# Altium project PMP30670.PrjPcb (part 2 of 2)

## Sheet PMP30670RevB_1.SchDoc: PMP30670RevA_1
size A3; Date: Not shown in title block; ApprovedBy: Not shown in title block; CheckedBy: Not shown in title block; Author: Not shown in title block; CompanyName: Not shown in title block; DrawnBy: M Zehendner; Engineer: Not shown in title block; Organization: Not shown in title block; Address1: Not shown in title block; Address2: Not shown in title block; Address3: Not shown in title block; Address4: Not shown in title block; DocumentNumber: 1; Revision: Use project parameter SCH_Rev; SheetNumber: 1; SheetTotal: 3; PageSetup: Record=PageOptions¦CenterHorizontal=True¦CenterVertical=True¦PrintScale=0.70¦XCorrection=1.00¦YCorrection=1.00¦PrintKind=0¦BorderSize=5000000¦LeftOffset=0¦BottomOffset=0¦Orientation=2¦PaperLength=1000¦PaperWidth=1000¦Scale=100¦PaperSource=15¦PrintQuality=600¦MediaType=1¦DitherType=10¦PaperKind=A4¦PrintScaleMode=1
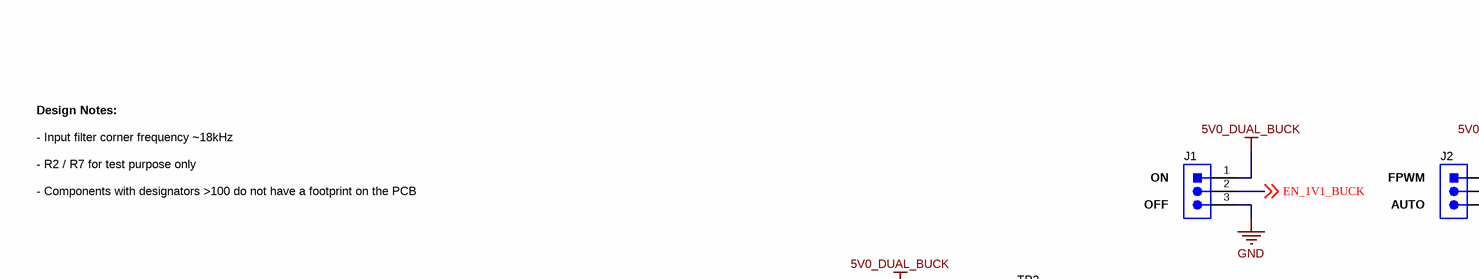
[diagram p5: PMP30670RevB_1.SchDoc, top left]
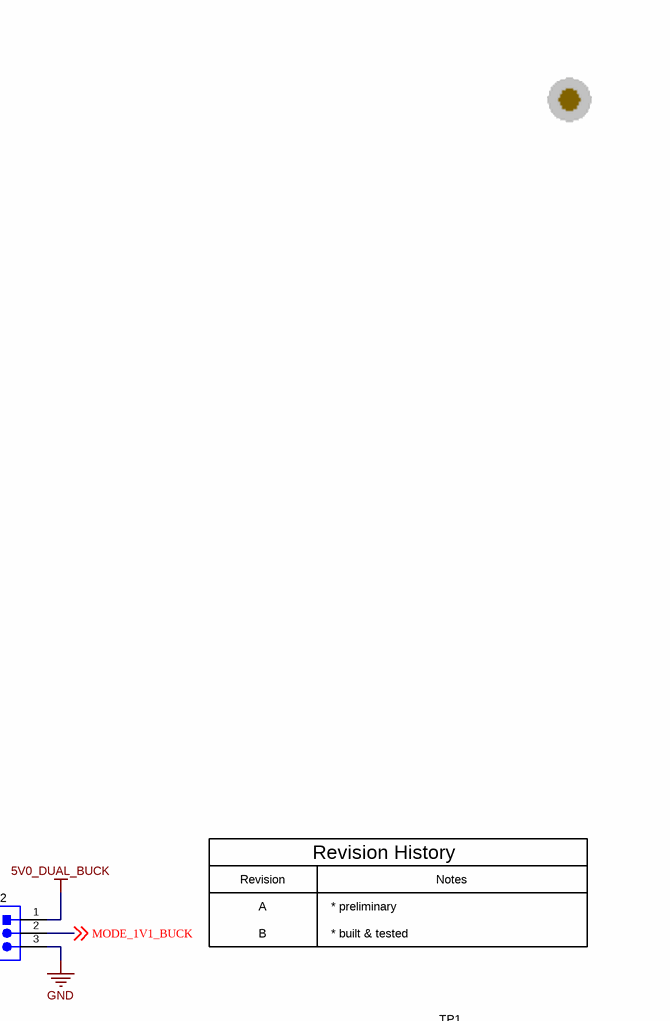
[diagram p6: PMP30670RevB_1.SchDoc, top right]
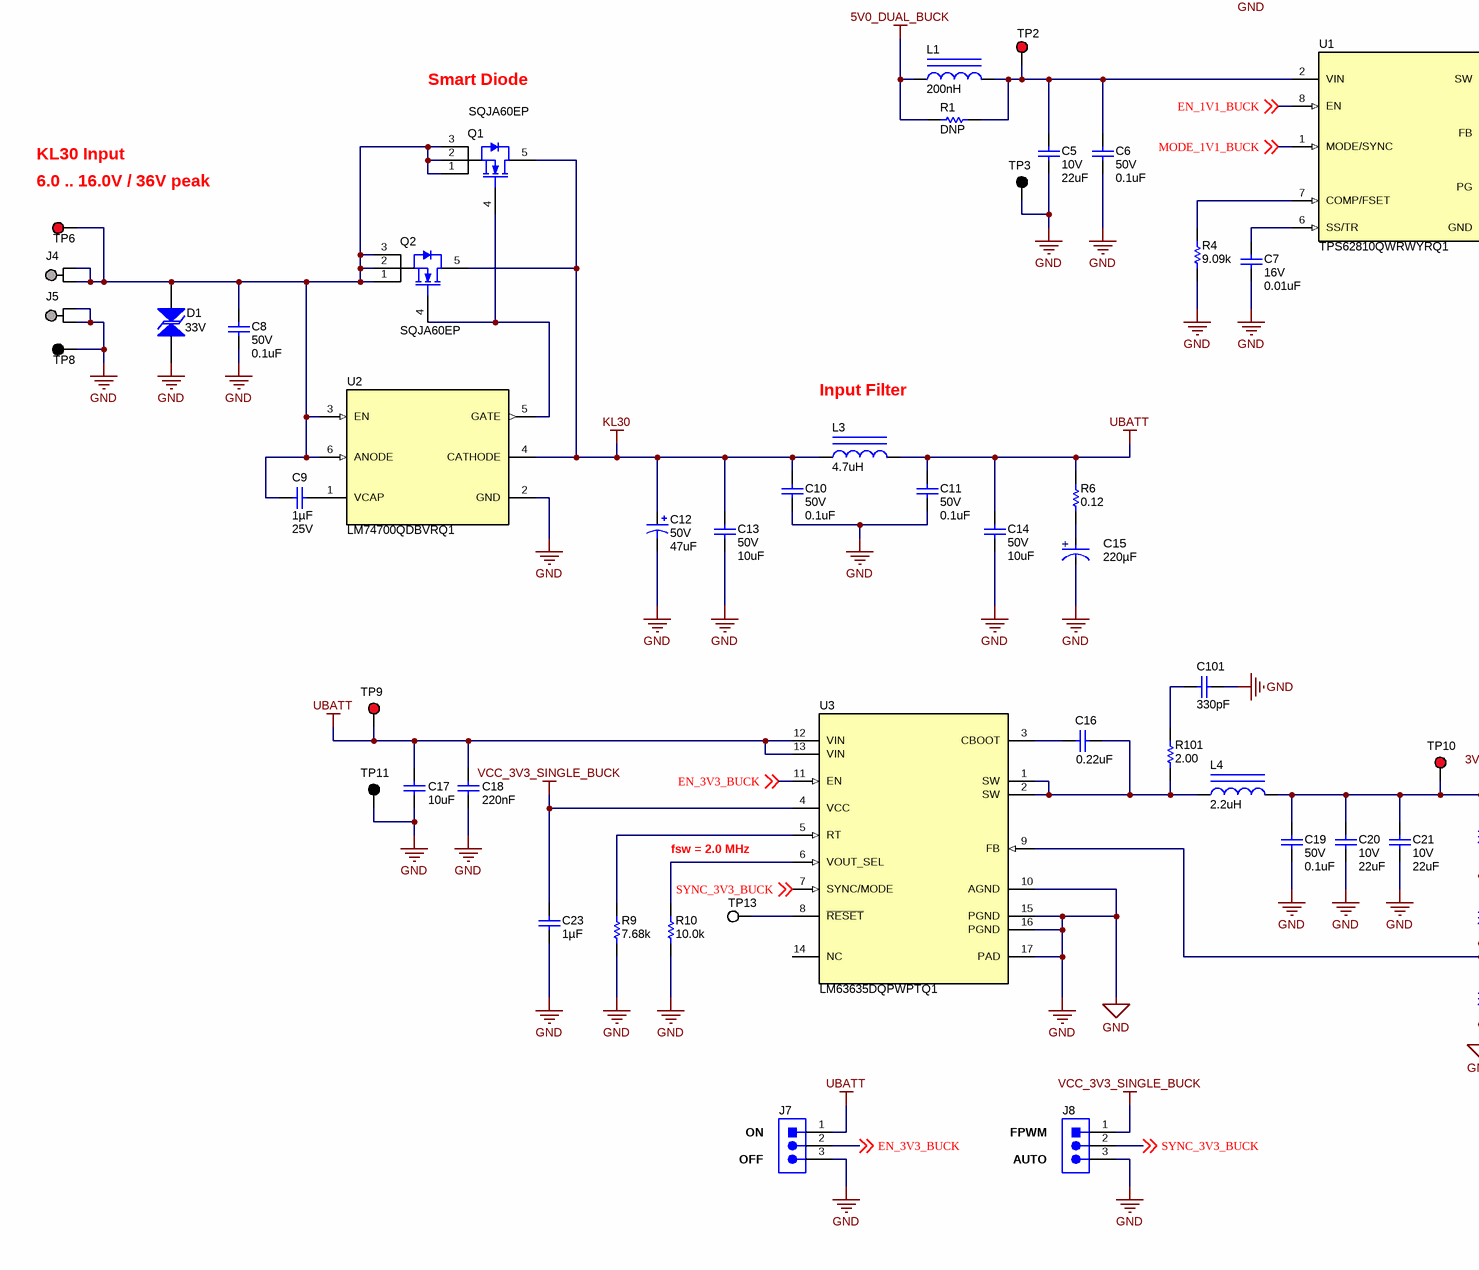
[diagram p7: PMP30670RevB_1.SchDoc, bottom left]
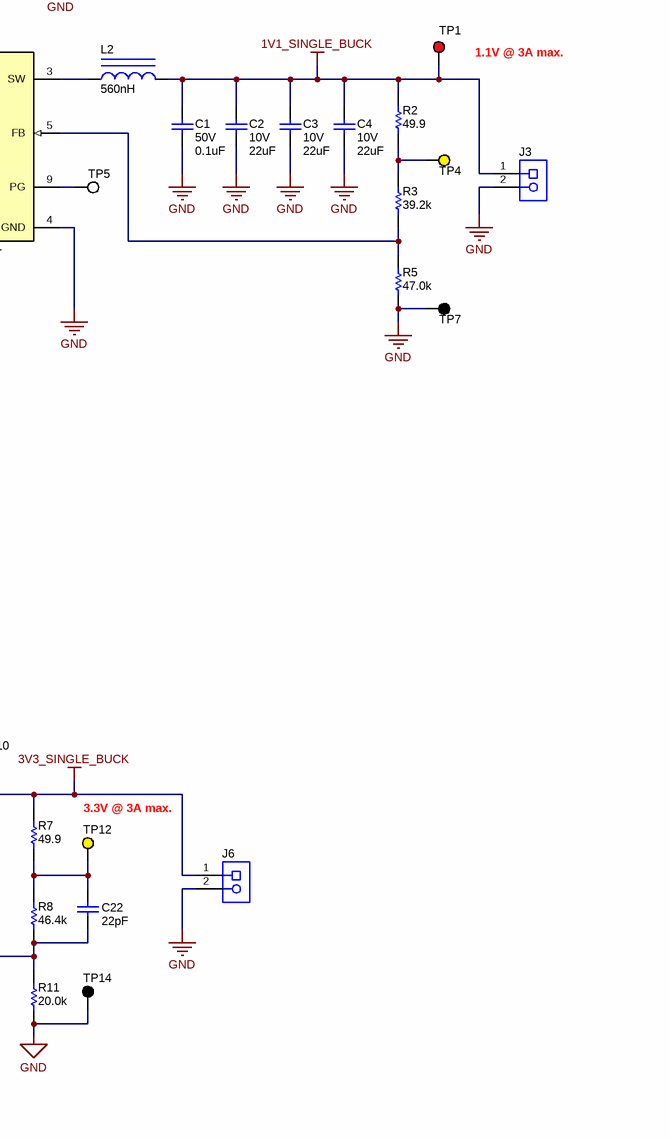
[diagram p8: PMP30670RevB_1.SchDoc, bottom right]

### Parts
C1  VDC_V: 50V  ValueDisplayed: 0.1uF  [0402]  (hidden comment: GRM155R71H104ME14D)
C2  VDC_V: 10V  ValueDisplayed: 22uF  [1206_180]  (hidden comment: GCM31CR71A226KE02)
C3  VDC_V: 10V  ValueDisplayed: 22uF  [1206_180]  (hidden comment: GCM31CR71A226KE02)
C4  VDC_V: 10V  ValueDisplayed: 22uF  [1206_180]  (hidden comment: GCM31CR71A226KE02)
C5  VDC_V: 10V  ValueDisplayed: 22uF  [1206_180]  (hidden comment: GCM31CR71A226KE02)
C6  VDC_V: 50V  ValueDisplayed: 0.1uF  [0402]  (hidden comment: GRM155R71H104ME14D)
C7  VDC_V: 16V  ValueDisplayed: 0.01uF  [0402]  (hidden comment: GRM155R71C103KA01D)
C8  VDC_V: 50V  ValueDisplayed: 0.1uF  [0402]  (hidden comment: GRM155R71H104ME14D)
C9  Cap_F: 1µF  VDC_V: 25V  [0603]  (hidden comment: GRM188R71E105KA12D)
C10  VDC_V: 50V  ValueDisplayed: 0.1uF  [0402]  (hidden comment: GRM155R71H104ME14D)
C11  VDC_V: 50V  ValueDisplayed: 0.1uF  [0402]  (hidden comment: GRM155R71H104ME14D)
C12  VDC_V: 50V  ValueDisplayed: 47uF  [SM_RADIAL_D8]  (hidden comment: EEE-FK1H470XP)
C13  VDC_V: 50V  ValueDisplayed: 10uF  [1210_270]  (hidden comment: GRM32ER71H106KA12L)
C14  VDC_V: 50V  ValueDisplayed: 10uF  [1210_270]  (hidden comment: GRM32ER71H106KA12L)
C15  Cap_F: 220µF  [FP-EEVTG1H221Q_RADIAL-Recommended_Land_Pattern]  (hidden comment: EEVTG1H221Q)
C16  ValueDisplayed: 0.22uF  [0402]  (hidden comment: GRM155R71C224KA12D)
C17  ValueDisplayed: 10uF  [1210_270]  (hidden comment: GRM32ER71H106KA12L)
C18  Cap_F: 220nF  [0603]  (hidden comment: GRM188R71H224KAC4D)
C19  VDC_V: 50V  ValueDisplayed: 0.1uF  [0402]  (hidden comment: GRM155R71H104ME14D)
C20  VDC_V: 10V  ValueDisplayed: 22uF  [1210_270]  (hidden comment: GRM32ER71A226ME20L)
C21  VDC_V: 10V  ValueDisplayed: 22uF  [1210_270]  (hidden comment: GRM32ER71A226ME20L)
C22  ValueDisplayed: 22pF  [0402]  (hidden comment: GRM1555C1H220FA01D)
C23  Cap_F: 1µF  [0805_HV]  (hidden comment: GRM21BR71A105KA01L)
C101  Cap_F: 330pF  [0603]  (hidden comment: GRM188R72E331KW07D)
D1  value 33V  [SMB-Bi]  (hidden comment: SMBJ33CA-13-F)
J1  800-10-003-10-001000  [Mill-Max_800-10-003-10-001000]  (value not drawn)
J2  800-10-003-10-001000  [Mill-Max_800-10-003-10-001000]  (value not drawn)
J3  691 101 710 002  [Wurth_691101710002]  (value not drawn)
J4  973 582-101  [HIRSCHMANN_973 582-101]  (value not drawn)
J5  973 582-100  [HIRSCHMANN_973 582-100]  (value not drawn)
J6  691 101 710 002  [Wurth_691101710002]  (value not drawn)
J7  800-10-003-10-001000  [Mill-Max_800-10-003-10-001000]  (value not drawn)
J8  800-10-003-10-001000  [Mill-Max_800-10-003-10-001000]  (value not drawn)
L1  ValueDisplayed: 200nH  [XPL2010]  (hidden comment: XPL2010-201MLB)
L2  ValueDisplayed: 560nH  [XEL4020]  (hidden comment: XEL4020-561MEB)
L3  ValueDisplayed: 4.7uH  [XAL1060]  (hidden comment: XAL1060-472MEB)
L4  ValueDisplayed: 2.2uH  [XAL5030]  (hidden comment: XEL5030-222MEB)
Q1  SQJA60EP  [PowerPAK_SO-8L]
Q2  SQJA60EP  [PowerPAK_SO-8L]
R1  ValueDisplayed: DNP  [1206]  (hidden comment: ERJ-8GEY0R00V)
R2  ValueDisplayed: 49.9  [0603]  (hidden comment: CRCW060349R9FKEA)
R3  ValueDisplayed: 39.2k  [0603]  (hidden comment: CRCW060339K2FKEA)
R4  ValueDisplayed: 9.09k  [0603]  (hidden comment: CRCW06039K09FKEA)
R5  ValueDisplayed: 47.0k  [0603]  (hidden comment: CRCW060347K0FKEA)
R6  ValueDisplayed: 0.12  [0603]  (hidden comment: ERJ-3RSFR12V)
R7  ValueDisplayed: 49.9  [0603]  (hidden comment: CRCW060349R9FKEA)
R8  ValueDisplayed: 46.4k  [0603]  (hidden comment: CRCW060346K4FKEA)
R9  ValueDisplayed: 7.68k  [0603]  (hidden comment: CRCW06037K68FKEA)
R10  ValueDisplayed: 10.0k  [0603]  (hidden comment: CRCW060310K0FKEA)
R11  ValueDisplayed: 20.0k  [0603]  (hidden comment: CRCW060320K0FKEA)
R101  ValueDisplayed: 2.00  [0603]  (hidden comment: CRCW06032R00FKEA)
TP1  5010  [Keystone5010]  (value not drawn)
TP2  5010  [Keystone5010]  (value not drawn)
TP3  5011  [Keystone5011]  (value not drawn)
TP4  5014  [Keystone5014]  (value not drawn)
TP5  5012  [Keystone5012]  (value not drawn)
TP6  5010  [Keystone5010]  (value not drawn)
TP7  5011  [Keystone5011]  (value not drawn)
TP8  5011  [Keystone5011]  (value not drawn)
TP9  5010  [Keystone5010]  (value not drawn)
TP10  5010  [Keystone5010]  (value not drawn)
TP11  5011  [Keystone5011]  (value not drawn)
TP12  5014  [Keystone5014]  (value not drawn)
TP13  5012  [Keystone5012]  (value not drawn)
TP14  5011  [Keystone5011]  (value not drawn)
U1  TPS62810QWRWYRQ1  [RWY0009A]
U2  LM74700QDBVRQ1  [DBV0006A_N]
U3  LM63635DQPWPTQ1  [PWP0016K_N]

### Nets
1V1_SINGLE_BUCK: C1.1 C2.1 C3.1 C4.1 J3.1 L2.2 R2.2 TP1.1
3V3_SINGLE_BUCK: C19.1 C20.1 C21.1 J6.1 L4.2 R7.2 TP10.1
5V0_DUAL_BUCK: J1.1 J2.1 L1.1 R1.1
GND: C1.2 C2.2 C3.2 C4.2 C5.2 C6.2 C7.2 C8.2 C10.2 C11.2 C12.2(-) C13.2 C14.2 C15.1(CATHODE) C17.2 C18.2 C19.2 C20.2 C21.2 C23.2 C101.1 D1.1 J1.3 J2.3 J3.2 J5.1 J5.2 J6.2 J7.3 J8.3 R4.1 R5.1 R9.1 R10.1 R11.1 TP3.1 TP7.1 TP8.1 TP11.1 TP14.1 U1.4(GND) U2.2(GND) U3.10(AGND) U3.15(PGND) U3.16(PGND) U3.17(PAD)
KL30: C10.1 C12.1(+) C13.1 L3.1 Q1.5(D) Q2.5(D) U2.4(CATHODE)
UBATT: C11.1 C14.1 C17.1 C18.1 J7.1 L3.2 R6.2 TP9.1 U3.12(VIN) U3.13(VIN)
VCC_3V3_SINGLE_BUCK: C23.1 J8.1 U3.4(VCC)
EN_1V1_BUCK: J1.2 U1.8(EN) ; off-sheet EN_1V1_BUCK
EN_3V3_BUCK: J7.2 U3.11(EN) ; off-sheet EN_3V3_BUCK
MODE_1V1_BUCK: J2.2 U1.1(MODE/SYNC) ; off-sheet MODE_1V1_BUCK
SYNC_3V3_BUCK: J8.2 U3.7(SYNC/MODE) ; off-sheet SYNC_3V3_BUCK
NetC5_1: C5.1 C6.1 L1.2 R1.2 TP2.1 U1.2(VIN)
NetC7_1: C7.1 U1.6(SS/TR)
NetC8_1: C8.1 C9.2 D1.2 J4.1 J4.2 Q1.1(S) Q1.2(S) Q1.3(S) Q2.1(S) Q2.2(S) Q2.3(S) TP6.1 U2.3(EN) U2.6(ANODE)
NetC9_1: C9.1 U2.1(VCAP)
NetC15_2: C15.2(ANODE) R6.1
NetC16_1: C16.1 U3.3(CBOOT)
NetC16_2: C16.2 L4.1 R101.1 U3.1(SW) U3.2(SW)
NetC22_1: C22.1 R7.1 R8.2 TP12.1
NetC22_2: C22.2 R8.1 R11.2 U3.9(FB)
NetC101_2: C101.2 R101.2
NetL2_1: L2.1 U1.3(SW)
NetQ1_4: Q1.4(G) Q2.4(G) U2.5(GATE)
NetR2_1: R2.1 R3.2 TP4.1
NetR3_1: R3.1 R5.2 U1.5(FB)
NetR4_2: R4.2 U1.7(COMP/FSET)
NetR9_2: R9.2 U3.5(RT)
NetR10_2: R10.2 U3.6(VOUT_SEL)
NetTP5_1: TP5.1 U1.9(PG)
NetTP13_1: TP13.1 U3.8(~{RESET})

Not connected (* = marked no-connect by the designer): U3 14(NC)

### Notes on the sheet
- Design Notes:
- - Input filter corner frequency
  8kHz
- - R2 / R7 for test purpose only
- Revision
- A
- * preliminary
- Revision History
- Notes
- - Components with designators >100 do not have a footprint on the PCB
- (near J1) ON
- (near J1) OFF
- (near J2) FPWM
- (near J2) AUTO
- B
- * built & tested
- (near TP1) 1.1V @ 3A max.
- Smart Diode
- KL30 Input
- (near TP6) 6.0 .. 16.0V / 36V peak
- Input Filter
- fsw = 2.0 MHz
- 3.3V @ 3A max.
- (near J7) ON
- (near J8) FPWM
- (near J7) OFF
- (near J8) AUTO

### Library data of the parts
C1 C6 C8 C10 C11 C19 = CMP-0006675-2: CAP, CERM, 0.1 uF, 50 V, +/- 20%, X7R, 0402; Manufacturer: MuRata; TaMin_C: -55°C; Polarized: N; SizeAreaWB_mm2: 3; Value1: Unknown; U/M: EA; Value: 0.1uF; TaMax_C: 125°C; SizeZ_mm: 0.6; SizeX_mm: 1; SizeY_mm: 0.5; Cap_F: 100nF; AEC Category: Q200
C2-C5 = CMP-0008811-2: CAP, CERM, 22 uF, 10 V, +/- 10%, X7R, AEC-Q200 Grade 1, 1206; Manufacturer: MuRata; TaMin_C: -55°C; Polarized: N; SizeAreaWB_mm2: 10.92; Value1: Unknown; U/M: EA; Value: 22uF; TaMax_C: 125°C; SizeZ_mm: 1.8; SizeX_mm: 3.2; SizeY_mm: 1.6; Cap_Case: 1206; SizeArea_mm2: 5.12; AEC Qualified: Y; Cap_F: 22µF; AEC Grade: 1; AEC Category: Q200
C7 = CMP-0006639-2: CAP, CERM, 0.01 uF, 16 V, +/- 10%, X7R, 0402; Manufacturer: MuRata; TaMin_C: -55°C; Polarized: N; SizeAreaWB_mm2: 3; Value1: Unknown; U/M: EA; Value: 0.01uF; TaMax_C: 125°C; SizeZ_mm: 0.6; SizeX_mm: 1; SizeY_mm: 0.5; Cap_F: 10nF; AEC Category: Q200
C9 = CMP-0007405-4: CAP, CERM, 1 uF, 25 V, +/- 10%, X7R, 0603; Manufacturer: MuRata; TaMin_C: -55°C; Polarized: N; SizeAreaWB_mm2: 4.68; Value1: Unknown; U/M: EA; Value: 1uF; TaMax_C: 125°C; SizeZ_mm: 1; SizeX_mm: 1.6; SizeY_mm: 0.8; SizeArea_mm2: 1.28; AEC Category: Q200
C12 = CMP-0011185-2: CAP, AL, 47 uF, 50 V, +/- 20%, 0.68 ohm, AEC-Q200 Grade 2, SMD; Manufacturer: Panasonic; TaMin_C: -55°C; ESR_ohm: 0.68; Polarized: Y; SizeAreaWB_mm2: 84.28; U/M: EA; Value: 47uF; TaMax_C: 105°C; SizeZ_mm: 7.7; SizeX_mm: 7.8; SizeY_mm: 6.6; Cap_Case: D8; SizeArea_mm2: 51.48; CompType: Capacitor; Cap_F: 47µF; IRMS_A: 195mA; AEC Grade: 2; AEC Category: Q200
C13 C14 = CMP-0009226-3: CAP, CERM, 10 uF, 50 V, +/- 10%, X7R, 1210; Manufacturer: MuRata; TaMin_C: -55°C; Polarized: N; SizeAreaWB_mm2: 14.7; Value1: Unknown; U/M: EA; Value: 10uF; TaMax_C: 125°C; SizeZ_mm: 2.7; SizeX_mm: 3.2; SizeY_mm: 2.5; Cap_Case: 1210; SizeArea_mm2: 8; Cap_F: 10µF; AEC Category: Q200
C15 = CMP-0087258-1: Cap Aluminum Lytic 220uF 50V 20% (12.5 X 13.5mm) SMD 0.23 Ohm 600mA 2000h 125C T/R; Manufacturer: Panasonic Electronic Components; SizeZ_mm: 14mm; AEC Grade: Grade 1; Symbol Name: SYM-EEVTG1H221Q; AEC Qualified: Yes
C16 = CMP-0006648-2: CAP, CERM, 0.22 uF, 16 V, +/- 10%, X7R, 0402; Manufacturer: MuRata; TaMin_C: -55°C; Polarized: N; SizeAreaWB_mm2: 3; Value1: Unknown; U/M: EA; Value: 0.22uF; TaMax_C: 125°C; SizeZ_mm: 0.6; SizeX_mm: 1; SizeY_mm: 0.5; Value2: 16V; Cap_F: 220nF; AEC Category: Q200
C17 = CMP-0009226-3: CAP, CERM, 10 uF, 50 V, +/- 10%, X7R, 1210; Manufacturer: MuRata; TaMin_C: -55°C; Polarized: N; SizeAreaWB_mm2: 14.7; Value1: Unknown; U/M: EA; Value: 10uF; TaMax_C: 125°C; SizeZ_mm: 2.7; SizeX_mm: 3.2; SizeY_mm: 2.5; Cap_Case: 1210; Value2: 50V; SizeArea_mm2: 8; Cap_F: 10µF; AEC Category: Q200
C18 = CMP-0007445-4: CAP, CERM, 0.22 uF, 50 V, +/- 10%, X7R, 0603; Manufacturer: MuRata; TaMin_C: -55°C; Polarized: N; SizeAreaWB_mm2: 4.68; Value1: Unknown; U/M: EA; Value: 0.22uF; TaMax_C: 125°C; SizeZ_mm: 1; SizeX_mm: 1.6; SizeY_mm: 0.8; Value2: 50V; SizeArea_mm2: 1.28; AEC Category: Q200
C20 C21 = CMP-0009219-2: CAP, CERM, 22 uF, 10 V, +/- 10%, X7R, 1210; Manufacturer: MuRata; TaMin_C: -55°C; ESR_ohm: 2m; Polarized: N; SizeAreaWB_mm2: 14.7; Value1: 0.002 ohm; U/M: EA; Value: 22uF; TaMax_C: 125°C; SizeZ_mm: 2.7; SizeX_mm: 3.2; SizeY_mm: 2.5; Cap_Case: 1210; SizeArea_mm2: 8; Cap_F: 22µF; IRMS_A: 3.2A; AEC Category: Q200
C22 = CMP-0006438-2: CAP, CERM, 22 pF, 50 V, +/- 1%, C0G/NP0, 0402; Manufacturer: MuRata; TaMin_C: -55°C; Polarized: N; SizeAreaWB_mm2: 3; Value1: Unknown; U/M: EA; Value: 22pF; TaMax_C: 125°C; SizeZ_mm: 0.6; SizeX_mm: 1; SizeY_mm: 0.5; Value2: 50V; AEC Category: Q200
C23 = CMP-0008313-2: CAP, CERM, 1 uF, 10 V, +/- 10%, X7R, 0805; Manufacturer: MuRata; TaMin_C: -55°C; ESR_ohm: 7m; Polarized: N; SizeAreaWB_mm2: 6.75; Value1: 0.007 ohm; U/M: EA; Value: 1uF; TaMax_C: 125°C; SizeZ_mm: 1.45; SizeX_mm: 2; SizeY_mm: 1.25; Cap_Case: 0805; Value2: 10V; SizeArea_mm2: 2.5; AEC Category: Q200
C101 = CMP-0007494-4: CAP, CERM, 330 pF, 250 V, +/- 10%, X7R, 0603; Manufacturer: MuRata; TaMin_C: -55°C; Polarized: N; SizeAreaWB_mm2: 4.68; Value1: Unknown; U/M: EA; Value: 330pF; TaMax_C: 125°C; SizeZ_mm: 1; SizeX_mm: 1.6; SizeY_mm: 0.8; Value2: 250V; SizeArea_mm2: 1.28; AEC Category: Q200
D1 = CMP-0005564-3: Diode, TVS, Bi, 33 V, SMB; Manufacturer: Diodes Inc.; SizeX_mm: 5.6; Ppk: 600W; SizeAreaWB_mm2: 44.156; SizeZ_mm: 2.6; SizeArea_mm2: 21.336; SizeY_mm: 3.81; AEC Category: Q101
J1 J2 J7 J8 = CMP-0055086-1: Header, 100mil, 3x1, TH; Manufacturer: Mill-Max; CNHeader: TRUE; Green_Lifecycle: Active; Green_REACh: Passed; CT: FALSE
J3 J6 = CMP-0054828-1: Terminal Block, 5 mm, 2x1, Tin, TH; Manufacturer: Wurth Elektronik; CNHeader: FALSE; Green_Lifecycle: Active; Green_REACh: Passed; CT: TRUE
J4 = CMP-0055403-2: TEST SOCKET, PCB, 4MM, RED; Manufacturer: Hirschmann; CT: TRUE; CompType: Banana Jack; CNHeader: FALSE
J5 = CMP-0055402-3: TEST SOCKET, PCB, 4MM, BLACK; Manufacturer: Hirschmann; CT: TRUE; CompType: Banana Jack; CNHeader: FALSE
L1 = CMP-0061169-1: Inductor, Shielded, Composite, 200 nH, 2.8 A, 0.02 ohm, SMD; Manufacturer: Coilcraft; Isat: 3.75A @ 30% inductance drop; Irms: 2.8A @ 40C rise; Green_Lifecycle: Not Set; SizeAreaWB_mm2: 8.7; DCR_ohm: 0.02; Green_REACh: Incomplete; Value: 200nH; Imax_A: 2.8A; SizeZ_mm: 1; SizeX_mm: 2; SizeY_mm: 1.9; SizeArea_mm2: 3.8; AEC Category: Q200
L2 = CMP-0061081-2: Inductor, Shielded, Composite, 560 nH, 11.3 A, 0.008 ohm, AEC-Q200 Grade 1, SMD; Manufacturer: Coilcraft; Isat: 11.3A @ 30% inductance drop; Irms: 13.8A @ 40C rise; SizeAreaWB_mm2: 25; DCR_ohm: 8m; Value: 560nH; Imax_A: 11.3A; SizeZ_mm: 2.1; SizeX_mm: 4; SizeArea_mm2: 16; AEC Qualified: Y; AEC Grade: 1; AEC Category: Q200
L3 = CMP-0060965-1: Inductor, Shielded, Composite, 4.7 uH, 14 A, 0.0098 ohm, AEC-Q200 Grade 1, SMD; Manufacturer: Coilcraft; Isat: 25A @ 30% inductance drop; Irms: 14A @ 40C rise; Green_Lifecycle: Not Set; SizeAreaWB_mm2: 159.6; DCR_ohm: 9.8m; Green_REACh: Incomplete; Value: 4.7uH; Imax_A: 14A; SizeZ_mm: 6; SizeX_mm: 11.3; SizeY_mm: 10; SizeArea_mm2: 113; Ind_H: 4.7µH; AEC Qualified: Y; AEC Grade: 1; AEC Category: Q200
L4 = CMP-0061001-2: Inductor, Shielded, Composite, 2.2 µH, 9.2 A, 0.01 ohm, AEC-Q200 Grade 1, SMD; Manufacturer: Coilcraft; PartNumber: XAL5030-222MEB; Isat: 12.9A @ 30% inductance drop; Irms: 9.2A @ 40C rise; Green_Lifecycle: Not Set; SizeAreaWB_mm2: 54.4544; DCR_ohm: 0.01; Green_REACh: Incomplete; Value: 2.2uH; Imax_A: 9.2A; SizeZ_mm: 3.1; SizeX_mm: 5.28; SizeY_mm: 5.48; SizeArea_mm2: 28.9344; Ind_H: 2.2µH; AEC Qualified: 1; AEC Category: Q200; AEC Grade: Y
Q1 Q2 = CMP-0000880-1: MOSFET, N-CH, 60 V, 30 A, AEC-Q101, PowerPAK_SO-8L; Alternate Manufacturer: None; Manufacturer: Vishay-Siliconix; SizeZ_mm: 1.14; ChType: N; Value2: 18 nC; Value1: 0.01; VdsMax_V: 60V; SizeX_mm: 6.15; SizeAreaWB_mm2: 58.1095; SizeY_mm: 5.13; Vgs_V: 20V; QgTyp_nC: 18; AEC Qualified: Y; Value: 60V; Rdson45_ohm: 0.016; SizeArea_mm2: 31.5495; AEC Category: Q101; IdsMax_A: 30A; U/M: EA
R1 = CMP-0018748-3: RES, 0, 5%, 0.25 W, AEC-Q200 Grade 0, 1206; Manufacturer: Panasonic; Power_W: 250mW; TempCo: 600 ppm/C; Value_Code: 0000; Value: 0; EIA_Code: E24; SizeX_mm: 3.2; SizeY_mm: 1.6; SizeZ_mm: 1.35; Value2: 0.25W; SizeArea_mm2: 5.12; AEC Qualified: Y; VDC_V: 200V; AEC Category: Q200; SizeAreaWB_mm2: 10.92
R2 R7 = CMP-0022448-4: RES, 49.9, 1%, 0.1 W, AEC-Q200 Grade 0, 0603; Manufacturer: Vishay-Dale; Power_W: 100mW; TempCo: 100 ppm/C; Value_Code: 49R9; Value: 49.9; EIA_Code: E96; SizeX_mm: 1.6; SizeY_mm: 0.8; SizeZ_mm: 1; Value2: 0.1W; SizeArea_mm2: 1.28; AEC Qualified: Y; VDC_V: 75V; AEC Category: Q200; AEC Grade: 0
R3 = CMP-0022369-4: RES, 39.2 k, 1%, 0.1 W, AEC-Q200 Grade 0, 0603; Manufacturer: Vishay-Dale; Power_W: 100mW; TempCo: 100 ppm/C; Value_Code: 39k2; Value: 39.2k; EIA_Code: E96; SizeX_mm: 1.6; SizeY_mm: 0.8; SizeZ_mm: 1; Value2: 0.1W; SizeArea_mm2: 1.28; AEC Qualified: Y; VDC_V: 75V; AEC Category: Q200; AEC Grade: 0
R4 = CMP-0022665-4: RES, 9.09 k, 1%, 0.1 W, AEC-Q200 Grade 0, 0603; Manufacturer: Vishay-Dale; Power_W: 100mW; TempCo: 100 ppm/C; Value_Code: 9k09; Value: 9.09k; EIA_Code: E96; SizeX_mm: 1.6; SizeY_mm: 0.8; SizeZ_mm: 1; Value2: 0.1W; SizeArea_mm2: 1.28; AEC Qualified: Y; VDC_V: 75V; AEC Category: Q200; AEC Grade: 0
R5 = CMP-0022438-4: RES, 47.0 k, 1%, 0.1 W, AEC-Q200 Grade 0, 0603; Manufacturer: Vishay-Dale; Power_W: 100mW; TempCo: 100 ppm/C; Value_Code: 47k0; Value: 47.0k; Res_ohm: 47k; SizeX_mm: 1.6; SizeY_mm: 0.8; SizeZ_mm: 1; Value2: 0.1W; SizeArea_mm2: 1.28; AEC Qualified: Y; VDC_V: 75V; AEC Grade: 0; AEC Category: Q200
R6 = CMP-0022722-1: RES, 0.12, 1%, 0.1 W, 0603; Manufacturer: Panasonic; Power_W: 100mW; TempCo: 300 ppm/C; Value_Code: R120; U/M: EA; Value: 0.12; EIA_Code: E96; SizeX_mm: 1.6; SizeY_mm: 0.8; SizeZ_mm: 1; Value2: 0.1W; SizeArea_mm2: 1.28; AEC Category: Q200
R8 = CMP-0022434-4: RES, 46.4 k, 1%, 0.1 W, AEC-Q200 Grade 0, 0603; Manufacturer: Vishay-Dale; Power_W: 100mW; TempCo: 100 ppm/C; Value_Code: 46k4; Value: 46.4k; EIA_Code: E96; SizeX_mm: 1.6; SizeY_mm: 0.8; SizeZ_mm: 1; Value2: 0.1W; SizeArea_mm2: 1.28; AEC Qualified: Y; VDC_V: 75V; AEC Category: Q200; AEC Grade: 0
R9 = CMP-0022602-4: RES, 7.68 k, 1%, 0.1 W, AEC-Q200 Grade 0, 0603; Manufacturer: Vishay-Dale; Power_W: 100mW; TempCo: 100 ppm/C; Value_Code: 7k68; Value: 7.68k; EIA_Code: E96; SizeX_mm: 1.6; SizeY_mm: 0.8; SizeZ_mm: 1; Value2: 0.1W; SizeArea_mm2: 1.28; AEC Qualified: Y; VDC_V: 75V; AEC Category: Q200; AEC Grade: 0
R10 = CMP-0021998-4: RES, 10.0 k, 1%, 0.1 W, AEC-Q200 Grade 0, 0603; Manufacturer: Vishay-Dale; Power_W: 100mW; TempCo: 100 ppm/C; Value_Code: 10k0; Value: 10.0k; EIA_Code: E96; Res_ohm: 10k; SizeX_mm: 1.6; SizeY_mm: 0.8; SizeZ_mm: 1; Value2: 0.1W; SizeArea_mm2: 1.28; AEC Qualified: Y; VDC_V: 75V; AEC Category: Q200; AEC Grade: 0
R11 = CMP-0022204-4: RES, 20.0 k, 1%, 0.1 W, AEC-Q200 Grade 0, 0603; Manufacturer: Vishay-Dale; Power_W: 100mW; TempCo: 100 ppm/C; Value_Code: 20k0; Value: 20.0k; EIA_Code: E96; Res_ohm: 20k; SizeX_mm: 1.6; SizeY_mm: 0.8; SizeZ_mm: 1; Value2: 0.1W; SizeArea_mm2: 1.28; AEC Qualified: Y; VDC_V: 75V; AEC Category: Q200; AEC Grade: 0
R101 = CMP-0022302-4: RES, 2.00, 1%, 0.1 W, AEC-Q200 Grade 0, 0603; Manufacturer: Vishay-Dale; Power_W: 100mW; TempCo: 100 ppm/C; Value_Code: 2R00; Value: 2.00; EIA_Code: E96; Res_ohm: 2; SizeX_mm: 1.6; SizeY_mm: 0.8; SizeZ_mm: 1; Value2: 0.1W; SizeArea_mm2: 1.28; AEC Qualified: Y; VDC_V: 75V; AEC Category: Q200; AEC Grade: 0
TP1 TP2 TP6 TP9 TP10 = CMP-0055147-1: Test Point, Multipurpose, Red, TH; Manufacturer: Keystone; CNHeader: FALSE; Green_Lifecycle: Active; Green_REACh: Passed; ContactFinish: Silver; CT: TRUE
TP3 TP7 TP8 TP11 TP14 = CMP-0055148-1: Test Point, Multipurpose, Black, TH; Manufacturer: Keystone; CNHeader: FALSE; Green_Lifecycle: Active; Green_REACh: Passed; ContactFinish: Silver; CT: TRUE
TP4 TP12 = CMP-0055151-1: Test Point, Multipurpose, Yellow, TH; Manufacturer: Keystone; CNHeader: FALSE; Green_Lifecycle: Active; Green_REACh: Passed; ContactFinish: Silver; CT: TRUE
TP5 TP13 = CMP-0055149-1: Test Point, Multipurpose, White, TH; Manufacturer: Keystone; CNHeader: FALSE; Green_Lifecycle: Active; Green_REACh: Passed; ContactFinish: Silver; CT: TRUE
U1 = CMP-0082642-1: Automotive Low Input Voltage, Adjustable-Frequency Step-down Converter, RWY0009A (VQFN-HR-9); Alternate Manufacturer: Texas Instruments; SizeAreaWB_mm2: 12; SizeZ_mm: 1; SizeX_mm: 2; SizeY_mm: 3; SizeArea_mm2: 6; CompType: IC; AEC Qualified: Y; AEC Category: Q200
U2 = CMP-0013281-4: Low Iq Always ON Smart Diode Controller, DBV0006A (SOT-23-6); Alternate PartNumber: LM74700QDBVTQ1; Manufacturer: Texas Instruments; SizeZ_mm: 1.45; SizeX_mm: 2.8; SizeY_mm: 2.9; SizeArea_mm2: 8.12; CompType: IC; SizeAreaWB_mm2: 14.82; AEC Category: Q200; AEC Qualified: Y
U3 = CMP-0080079-4: 3.5-V to 36-V, 3.5-A Synchronous Step-Down Voltage Regulator with Spread Spectrum, PWP0016D (TSSOP-16); Alternate Manufacturer: Texas Instruments; SizeAreaWB_mm2: 58.8; SizeZ_mm: 1.2; SizeX_mm: 6.4; SizeY_mm: 5; SizeArea_mm2: 32; CompType: IC; AEC Qualified: Y; AEC Category: Q200; Rating: Automotive

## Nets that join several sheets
3V3_DUAL_BUCK: PMP30670RevB_3 (R40.1 TP27.1), PMP30670RevB_2 (11 pins)
5V0_DUAL_BUCK: PMP30670RevB_2 (8 pins), PMP30670RevB_1 (J1.1 J2.1 L1.1 R1.1)
GND: PMP30670RevB_3 (24 pins), PMP30670RevB_2 (57 pins), PMP30670RevB_1 (46 pins)
KL30: PMP30670RevB_3 (J17.1), PMP30670RevB_1 (7 pins)
UBATT: PMP30670RevB_2 (30 pins), PMP30670RevB_1 (10 pins)

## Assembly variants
001: not fitted FID1 FID2 FID3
